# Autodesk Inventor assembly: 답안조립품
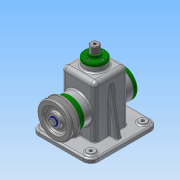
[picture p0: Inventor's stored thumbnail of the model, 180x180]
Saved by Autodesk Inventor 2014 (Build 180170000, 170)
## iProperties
Created: 2015-12
Part Number: 답안조립품
Document SubType Name: Assembly
Designer: Administrator
Author: Administrator
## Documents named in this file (19)
- D:\451225V1007\답안조립품.iam
- D:\451225V1007\1-본체.ipt
- D:\451225V1007\고정핀.ipt
- D:\451225V1007\뒤커버.ipt
- D:\451225V1007\링크.ipt
- D:\451225V1007\멈춤링 6 x 5.ipt
- D:\451225V1007\멈춤링 15 x 1.ipt
- D:\451225V1007\베어링 15 x 35 x 11.ipt
- D:\451225V1007\볼트 M3 x 8.ipt
- D:\451225V1007\볼트 M4 x 10.ipt
- D:\451225V1007\볼트 M6 x 12.ipt
- D:\451225V1007\상부부시.ipt
- D:\451225V1007\슬라이드바.ipt
- D:\451225V1007\앞커버.ipt
- D:\451225V1007\오일실 15 25 7.ipt
- D:\451225V1007\와셔.ipt
- D:\451225V1007\키 5 x 5 x 14.ipt
- D:\451225V1007\편심축.ipt
- D:\451225V1007\V-벨트풀리.ipt
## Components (16 placed, 6 different names)
1. 1-본체:1
2. 고정핀:1
3. ISO 4018 M6 x 12:1
4. V-벨트풀리:1 — 각도:2
5. ISO 4762 M4 x 10:2
6. ISO 4762 M4 x 10:3
7. ISO 4762 M4 x 10:4
8. ISO 4762 M4 x 10:5
9. ISO 4762 M4 x 10:1
10. ISO 4762 M4 x 10:6
11. ISO 4762 M4 x 10:7
12. ISO 4762 M4 x 10:8
13. ISO 4762 M3 x 8:1
14. ISO 4762 M3 x 8:2
15. ISO 4762 M3 x 8:3
16. ISO 4762 M3 x 8:4
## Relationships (1: Angle 1)
- 각도:2 [Angle]: V-벨트풀리:1
